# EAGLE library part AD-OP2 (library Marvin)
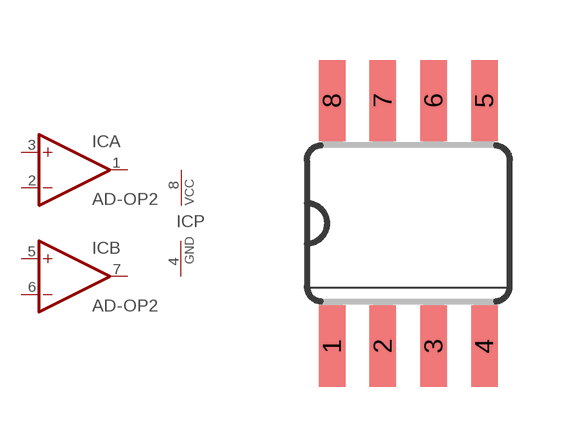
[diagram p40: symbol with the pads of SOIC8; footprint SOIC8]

Designator prefix IC; gates P=PWRGND A=OP B=OP

## AD-OP2S  [SOIC8]
1  A:OUT  out
2  A:-IN  in
3  A:+IN  in
4  P:GND  pwr
5  B:+IN  in
6  B:-IN  in
7  B:OUT  out
8  P:VCC  pwr

## Footprint SOIC8 (pad centres in mm)
smd 0.66 x 2.032: 1 -1.905,-3.073; 2 -0.635,-3.073; 3 0.635,-3.073; 4 1.905,-3.073; 5 1.905,3.073; 6 0.635,3.073; 7 -0.635,3.073; 8 -1.905,3.073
